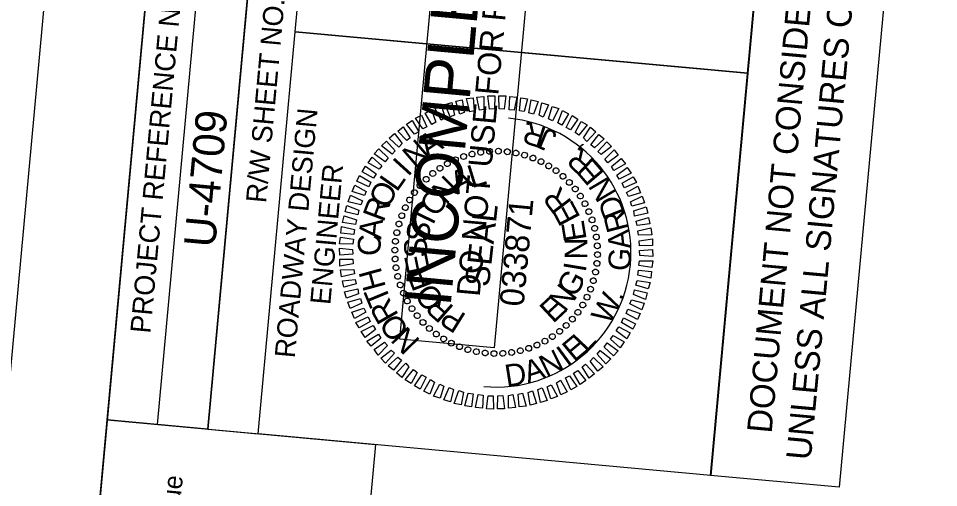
# Model space of a CAD drawing. Extents: x 2011671 to 2012922, y 444832 to 446720.
# Drawn here: x 2011808.5 to 2012036.3, y 446477.1 to 446593.3 of the extents above; entities that cross this region are included whole.
import ezdxf

# ---------------------------------------------------------------- set-up
doc = ezdxf.new("R2010")
doc.units = 0
for name, color, linetype in [('Old_Level_2', 7, 'Continuous'), ('Old_Level_58', 7, 'Continuous'), ('Scratch_Level_0', 7, 'Continuous'), ('Sheet Data Field CELL', 7, 'Continuous'), ('Sheet Plan And Profile CELL', 7, 'Continuous'), ('Sheet Plot Border Outside CELL', 7, 'Continuous'), ('Sheet Professional Seal CELL', 7, 'Continuous'), ('Sheet Profile Grid Minor CELL', 7, 'Continuous'), ('Sheet Sticker Exception Certification CELL', 7, 'Continuous'), ('Sheet Sticker Incomplete CELL', 7, 'Continuous')]:
    doc.layers.add(name, color=color, linetype=linetype)

msp = doc.modelspace()

# ---------------------------------------------------------------- linework, layer by layer
at = {"layer": 'Old_Level_58'}
msp.add_lwpolyline([(2011812.16, 446294.64), (2011830.48, 446493.85), (2011896.89, 446487.74), (2011878.57, 446288.53)], close=True, dxfattribs=at)
at = {"layer": 'Scratch_Level_0'}
msp.add_arc((2011926.78, 446535.36), 33.36, 264.7467, 84.7467, dxfattribs=at)
at = {"layer": 'Sheet Plan And Profile CELL'}
for p, q in [((2011842.98, 446492.7), (2011861.29, 446691.91)), ((2011855.42, 446491.55), (2011873.74, 446690.76)), ((2011877.03, 446590.04), (2011989.01, 446579.74)), ((2011855.42, 446491.55), (2011867.87, 446490.41))]:
    msp.add_line(p, q, dxfattribs=at)
for points in [[(2011848.79, 446693.05), (2011711.46, 445199.36), (2012757.04, 445103.22), (2012894.38, 446596.92)], [(2011830.48, 446493.85), (2011848.79, 446693.05), (2011873.74, 446690.76), (2011855.42, 446491.55)], [(2011877.03, 446590.04), (2011886.19, 446689.62), (2011998.21, 446679.32), (2011989.06, 446579.74)], [(2011867.87, 446490.41), (2011877.03, 446590.04), (2011989.06, 446579.74), (2011979.9, 446480.11)]]:
    msp.add_lwpolyline(points, close=True, dxfattribs=at)
at = {"layer": 'Sheet Plot Border Outside CELL'}
msp.add_lwpolyline([(2012765.92, 444926.66), (2012921.57, 446619.52), (2011826.19, 446720.24), (2011670.54, 445027.38)], close=True, dxfattribs=at)
at = {"layer": 'Sheet Professional Seal CELL'}
for p, q in [((2011920.79, 446559.76), (2011920.79, 446559.76)), ((2011922.94, 446560.17), (2011922.94, 446560.17)), ((2011925.17, 446560.37), (2011925.17, 446560.37)), ((2011927.34, 446560.47), (2011927.34, 446560.47)), ((2011929.53, 446560.32), (2011929.53, 446560.32)), ((2011931.71, 446559.97), (2011931.71, 446559.97)), ((2011916.7, 446558.33), (2011916.7, 446558.33)), ((2011918.73, 446559.15), (2011918.73, 446559.15)), ((2011933.82, 446559.42), (2011933.82, 446559.42)), ((2011935.87, 446558.78), (2011935.87, 446558.78)), ((2011937.89, 446557.89), (2011937.89, 446557.89)), ((2011912.84, 446556.28), (2011912.84, 446556.28)), ((2011914.7, 446557.36), (2011914.7, 446557.36)), ((2011939.8, 446556.81), (2011939.8, 446556.81)), ((2011941.65, 446555.64), (2011941.65, 446555.64)), ((2011909.43, 446553.53), (2011909.43, 446553.53)), ((2011911.06, 446554.93), (2011911.06, 446554.93)), ((2011943.33, 446554.23), (2011943.33, 446554.23)), ((2011907.92, 446551.91), (2011907.92, 446551.91)), ((2011944.95, 446552.72), (2011944.95, 446552.72)), ((2011946.36, 446551.09), (2011946.36, 446551.09)), ((2011905.34, 446548.38), (2011905.34, 446548.38)), ((2011906.51, 446550.23), (2011906.51, 446550.23)), ((2011947.7, 446549.31), (2011947.7, 446549.31)), ((2011904.26, 446546.47), (2011904.26, 446546.47)), ((2011948.78, 446547.45), (2011948.78, 446547.45)), ((2011903.37, 446544.44), (2011903.37, 446544.44)), ((2011949.75, 446545.45), (2011949.75, 446545.45)), ((2011902.73, 446542.39), (2011902.73, 446542.39)), ((2011950.57, 446543.42), (2011950.57, 446543.42)), ((2011902.18, 446540.29), (2011902.18, 446540.29)), ((2011951.19, 446541.35), (2011951.19, 446541.35)), ((2011951.59, 446539.21), (2011951.59, 446539.21)), ((2011901.83, 446538.11), (2011901.83, 446538.11)), ((2011951.79, 446536.98), (2011951.79, 446536.98)), ((2011901.68, 446535.91), (2011901.68, 446535.91)), ((2011926.78, 446535.36), (2011926.78, 446535.36)), ((2011951.89, 446534.81), (2011951.89, 446534.81)), ((2011901.78, 446533.75), (2011901.78, 446533.75)), ((2011951.74, 446532.62), (2011951.74, 446532.62)), ((2011901.98, 446531.52), (2011901.98, 446531.52)), ((2011951.39, 446530.44), (2011951.39, 446530.44)), ((2011902.38, 446529.37), (2011902.38, 446529.37)), ((2011950.84, 446528.33), (2011950.84, 446528.33)), ((2011903, 446527.31), (2011903, 446527.31)), ((2011950.2, 446526.28), (2011950.2, 446526.28)), ((2011903.81, 446525.27), (2011903.81, 446525.27)), ((2011904.79, 446523.28), (2011904.79, 446523.28)), ((2011949.31, 446524.25), (2011949.31, 446524.25)), ((2011905.87, 446521.42), (2011905.87, 446521.42)), ((2011948.23, 446522.34), (2011948.23, 446522.34)), ((2011907.21, 446519.64), (2011907.21, 446519.64)), ((2011945.65, 446518.82), (2011945.65, 446518.82)), ((2011947.06, 446520.49), (2011947.06, 446520.49)), ((2011908.62, 446518), (2011908.62, 446518)), ((2011910.24, 446516.5), (2011910.24, 446516.5)), ((2011944.14, 446517.2), (2011944.14, 446517.2)), ((2011911.92, 446515.09), (2011911.92, 446515.09)), ((2011940.73, 446514.45), (2011940.73, 446514.45)), ((2011942.51, 446515.79), (2011942.51, 446515.79)), ((2011913.77, 446513.91), (2011913.77, 446513.91)), ((2011915.68, 446512.84), (2011915.68, 446512.84)), ((2011917.7, 446511.95), (2011917.7, 446511.95)), ((2011936.87, 446512.39), (2011936.87, 446512.39)), ((2011938.87, 446513.36), (2011938.87, 446513.36)), ((2011919.75, 446511.31), (2011919.75, 446511.31)), ((2011921.86, 446510.76), (2011921.86, 446510.76)), ((2011924.04, 446510.41), (2011924.04, 446510.41)), ((2011926.23, 446510.26), (2011926.23, 446510.26)), ((2011928.4, 446510.36), (2011928.4, 446510.36)), ((2011930.63, 446510.56), (2011930.63, 446510.56)), ((2011932.78, 446510.96), (2011932.78, 446510.96)), ((2011934.84, 446511.58), (2011934.84, 446511.58))]:
    msp.add_line(p, q, dxfattribs=at)
for points in [[(2011920.25, 446570.21), (2011919.4, 446573.5), (2011921.07, 446573.65), (2011921.33, 446570.46)], [(2011922.69, 446570.59), (2011922.03, 446573.81), (2011923.76, 446573.95), (2011923.77, 446570.79)], [(2011925.12, 446570.81), (2011924.72, 446574.11), (2011926.43, 446574.11), (2011926.34, 446570.9)], [(2011927.54, 446570.89), (2011927.44, 446574.17), (2011929.14, 446574.11), (2011928.75, 446570.88)], [(2011930.04, 446570.71), (2011930.18, 446573.96), (2011931.88, 446573.81), (2011931.23, 446570.6)], [(2011932.52, 446570.43), (2011932.92, 446573.66), (2011934.55, 446573.41), (2011933.71, 446570.23)], [(2011913.13, 446568.15), (2011911.64, 446571.1), (2011913.25, 446571.6), (2011914.13, 446568.66)], [(2011915.36, 446568.95), (2011914.14, 446572.02), (2011915.79, 446572.53), (2011916.5, 446569.35)], [(2011917.78, 446569.63), (2011916.77, 446572.79), (2011918.36, 446573.19), (2011918.88, 446570.03)], [(2011934.89, 446569.97), (2011935.48, 446573.13), (2011937.15, 446572.77), (2011936.06, 446569.61)], [(2011937.39, 446569.33), (2011938.07, 446572.38), (2011939.73, 446571.88), (2011938.4, 446568.84)], [(2011939.72, 446568.47), (2011940.65, 446571.49), (2011942.26, 446571), (2011940.73, 446567.97)], [(2011908.66, 446565.95), (2011906.79, 446568.58), (2011908.32, 446569.4), (2011909.66, 446566.46)], [(2011910.82, 446567.06), (2011909.17, 446569.87), (2011910.75, 446570.68), (2011911.88, 446567.66)], [(2011942.04, 446567.5), (2011943.22, 446570.51), (2011944.71, 446569.72), (2011943.04, 446566.86)], [(2011944.14, 446566.3), (2011945.57, 446569.29), (2011947.04, 446568.4), (2011945.19, 446565.7)], [(2011906.58, 446564.64), (2011904.55, 446567.13), (2011905.99, 446568.05), (2011907.64, 446565.24)], [(2011946.34, 446565.1), (2011947.85, 446567.82), (2011949.32, 446566.93), (2011947.23, 446564.41)], [(2011902.72, 446561.43), (2011900.32, 446563.7), (2011901.62, 446564.79), (2011903.55, 446562.3)], [(2011904.63, 446563.06), (2011902.48, 446565.41), (2011903.79, 446566.5), (2011905.49, 446563.73)], [(2011948.37, 446563.71), (2011950.12, 446566.36), (2011951.42, 446565.23), (2011949.19, 446562.83)], [(2011950.22, 446562.03), (2011952.16, 446564.56), (2011953.52, 446563.48), (2011951.11, 446561.29)], [(2011901, 446559.68), (2011898.43, 446561.77), (2011899.65, 446562.96), (2011901.79, 446560.56)], [(2011951.98, 446560.36), (2011954.16, 446562.77), (2011955.35, 446561.56), (2011952.81, 446559.58)], [(2011899.32, 446557.77), (2011896.59, 446559.78), (2011897.76, 446560.98), (2011900.02, 446558.81)], [(2011953.71, 446558.44), (2011955.99, 446560.8), (2011957.02, 446559.45), (2011954.43, 446557.57)], [(2011897.8, 446555.95), (2011895.08, 446557.56), (2011896.07, 446558.97), (2011898.48, 446556.84)], [(2011955.3, 446556.64), (2011957.69, 446558.63), (2011958.78, 446557.33), (2011955.91, 446555.63)], [(2011896.44, 446553.77), (2011893.62, 446555.28), (2011894.46, 446556.76), (2011897.09, 446554.81)], [(2011956.66, 446554.51), (2011959.25, 446556.43), (2011960.17, 446554.99), (2011957.22, 446553.5)], [(2011895.29, 446551.61), (2011892.26, 446553.05), (2011892.98, 446554.39), (2011895.74, 446552.73)], [(2011957.98, 446552.48), (2011960.69, 446554.09), (2011961.52, 446552.71), (2011958.48, 446551.33)], [(2011894.19, 446549.46), (2011891.17, 446550.49), (2011891.81, 446551.98), (2011894.63, 446550.47)], [(2011959.03, 446550.17), (2011961.88, 446551.77), (2011962.54, 446550.15), (2011959.54, 446549.17)], [(2011893.32, 446547.13), (2011890.13, 446547.92), (2011890.68, 446549.58), (2011893.67, 446548.15)], [(2011960.02, 446547.92), (2011962.96, 446549.26), (2011963.51, 446547.65), (2011960.37, 446546.79)], [(2011892.54, 446544.64), (2011889.39, 446545.38), (2011889.79, 446547), (2011892.8, 446545.82)], [(2011960.87, 446545.63), (2011963.88, 446546.66), (2011964.34, 446545.12), (2011961.05, 446544.36)], [(2011891.92, 446542.28), (2011888.7, 446542.78), (2011889.15, 446544.4), (2011892.23, 446543.46)], [(2011961.44, 446543.12), (2011964.53, 446543.99), (2011964.84, 446542.41), (2011961.69, 446542.04)], [(2011891.54, 446539.81), (2011888.31, 446540.11), (2011888.51, 446541.74), (2011891.7, 446541)], [(2011961.87, 446540.67), (2011965.1, 446541.43), (2011965.29, 446539.7), (2011962.02, 446539.6)], [(2011891.27, 446537.42), (2011888.01, 446537.47), (2011888.22, 446539.11), (2011891.43, 446538.61)], [(2011962.2, 446538.23), (2011965.46, 446538.74), (2011965.45, 446537.08), (2011962.24, 446537.02)], [(2011891.29, 446534.91), (2011888.06, 446534.66), (2011888.01, 446536.37), (2011891.25, 446536.12)], [(2011962.28, 446535.81), (2011965.51, 446536.07), (2011965.56, 446534.36), (2011962.31, 446534.61)], [(2011891.37, 446532.49), (2011888.11, 446531.99), (2011888.12, 446533.65), (2011891.33, 446533.7)], [(2011962.3, 446533.3), (2011965.55, 446533.25), (2011965.35, 446531.62), (2011962.14, 446532.11)], [(2011891.7, 446530.05), (2011888.47, 446529.3), (2011888.28, 446531.02), (2011891.55, 446531.12)], [(2011962.03, 446530.92), (2011965.26, 446530.62), (2011965.06, 446528.98), (2011961.87, 446529.73)], [(2011892.13, 446527.6), (2011889.04, 446526.73), (2011888.73, 446528.32), (2011891.88, 446528.68)], [(2011961.65, 446528.44), (2011964.87, 446527.94), (2011964.42, 446526.33), (2011961.34, 446527.26)], [(2011892.7, 446525.09), (2011889.69, 446524.06), (2011889.23, 446525.61), (2011892.52, 446526.36)], [(2011961.03, 446526.09), (2011964.17, 446525.35), (2011963.77, 446523.73), (2011960.77, 446524.91)], [(2011893.55, 446522.8), (2011890.61, 446521.47), (2011890.06, 446523.07), (2011893.2, 446523.94)], [(2011960.25, 446523.6), (2011963.44, 446522.8), (2011962.88, 446521.15), (2011959.9, 446522.58)], [(2011894.54, 446520.55), (2011891.69, 446518.96), (2011891.03, 446520.57), (2011894.03, 446521.55)], [(2011959.38, 446521.27), (2011962.4, 446520.24), (2011961.76, 446518.74), (2011958.94, 446520.26)], [(2011895.59, 446518.25), (2011892.88, 446516.64), (2011892.05, 446518.02), (2011895.09, 446519.4)], [(2011958.28, 446519.11), (2011961.31, 446517.68), (2011960.58, 446516.34), (2011957.83, 446518)], [(2011896.91, 446516.22), (2011894.32, 446514.3), (2011893.4, 446515.74), (2011896.35, 446517.22)], [(2011957.13, 446516.96), (2011959.95, 446515.44), (2011959.11, 446513.96), (2011956.48, 446515.91)], [(2011898.27, 446514.08), (2011895.87, 446512.09), (2011894.79, 446513.4), (2011897.66, 446515.09)], [(2011955.77, 446514.77), (2011958.49, 446513.17), (2011957.5, 446511.75), (2011955.09, 446513.88)], [(2011899.86, 446512.28), (2011897.58, 446509.93), (2011896.55, 446511.28), (2011899.13, 446513.15)], [(2011954.25, 446512.95), (2011956.98, 446510.95), (2011955.81, 446509.75), (2011953.55, 446511.91)], [(2011901.59, 446510.36), (2011899.41, 446507.95), (2011898.22, 446509.17), (2011900.76, 446511.14)], [(2011952.57, 446511.05), (2011955.14, 446508.96), (2011953.92, 446507.76), (2011951.78, 446510.17)], [(2011903.34, 446508.7), (2011901.4, 446506.16), (2011900.05, 446507.24), (2011902.46, 446509.43)], [(2011905.2, 446507.02), (2011903.45, 446504.37), (2011902.15, 446505.49), (2011904.38, 446507.9)], [(2011948.94, 446507.67), (2011951.09, 446505.31), (2011949.78, 446504.23), (2011948.08, 446506.99)], [(2011950.85, 446509.3), (2011953.25, 446507.02), (2011951.95, 446505.94), (2011950.02, 446508.42)], [(2011907.23, 446505.63), (2011905.72, 446502.9), (2011904.25, 446503.79), (2011906.34, 446506.31)], [(2011946.99, 446506.09), (2011949.02, 446503.59), (2011947.58, 446502.67), (2011945.93, 446505.48)], [(2011909.43, 446504.42), (2011908, 446501.44), (2011906.53, 446502.33), (2011908.38, 446505.02)], [(2011911.53, 446503.22), (2011910.35, 446500.22), (2011908.86, 446501.01), (2011910.53, 446503.87)], [(2011913.85, 446502.26), (2011912.92, 446499.23), (2011911.31, 446499.73), (2011912.84, 446502.75)], [(2011942.75, 446503.67), (2011944.4, 446500.85), (2011942.82, 446500.05), (2011941.69, 446503.06)], [(2011944.91, 446504.77), (2011946.78, 446502.14), (2011945.25, 446501.33), (2011943.91, 446504.26)], [(2011916.18, 446501.39), (2011915.5, 446498.34), (2011913.84, 446498.84), (2011915.17, 446501.89)], [(2011918.68, 446500.76), (2011918.09, 446497.6), (2011916.42, 446497.95), (2011917.51, 446501.12)], [(2011921.05, 446500.29), (2011920.65, 446497.06), (2011919.02, 446497.31), (2011919.86, 446500.5)], [(2011933.32, 446500.52), (2011934.17, 446497.23), (2011932.5, 446497.08), (2011932.24, 446500.27)], [(2011935.78, 446501.09), (2011936.8, 446497.94), (2011935.21, 446497.53), (2011934.69, 446500.69)], [(2011938.21, 446501.78), (2011939.43, 446498.7), (2011937.78, 446498.2), (2011937.07, 446501.38)], [(2011940.44, 446502.57), (2011941.93, 446499.63), (2011940.32, 446499.12), (2011939.44, 446502.06)], [(2011923.53, 446500.01), (2011923.39, 446496.76), (2011921.69, 446496.92), (2011922.34, 446500.12)], [(2011926.03, 446499.83), (2011926.13, 446496.56), (2011924.43, 446496.62), (2011924.82, 446499.84)], [(2011928.45, 446499.91), (2011928.85, 446496.61), (2011927.14, 446496.62), (2011927.23, 446499.82)], [(2011930.88, 446500.14), (2011931.53, 446496.92), (2011929.81, 446496.77), (2011929.8, 446499.94)]]:
    msp.add_lwpolyline(points, close=True, dxfattribs=at)
for centre, major_axis in [((2011918.72, 446559.11), (-0.231, 0.682)), ((2011920.82, 446559.72), (-0.171, 0.699)), ((2011922.97, 446560.15), (-0.109, 0.712)), ((2011925.15, 446560.39), (-0.047, 0.718)), ((2011927.33, 446560.44), (0.016, 0.72)), ((2011929.52, 446560.29), (0.078, 0.716)), ((2011931.68, 446559.96), (0.141, 0.706)), ((2011933.8, 446559.44), (0.202, 0.691)), ((2011914.72, 446557.35), (-0.346, 0.631)), ((2011916.69, 446558.32), (-0.29, 0.659)), ((2011935.88, 446558.74), (0.261, 0.671)), ((2011937.88, 446557.86), (0.318, 0.646)), ((2011939.8, 446556.8), (0.374, 0.616)), ((2011911.09, 446554.92), (-0.451, 0.562)), ((2011912.85, 446556.22), (-0.4, 0.599)), ((2011941.62, 446555.59), (0.426, 0.581)), ((2011909.44, 446553.48), (-0.498, 0.52)), ((2011943.32, 446554.22), (0.475, 0.541)), ((2011944.9, 446552.7), (0.52, 0.498)), ((2011906.56, 446550.19), (-0.581, 0.426)), ((2011907.93, 446551.9), (-0.541, 0.475)), ((2011946.35, 446551.06), (0.562, 0.451)), ((2011905.34, 446548.37), (-0.616, 0.374)), ((2011947.64, 446549.3), (0.599, 0.4)), ((2011904.29, 446546.46), (-0.646, 0.318)), ((2011948.77, 446547.42), (0.631, 0.346)), ((2011949.74, 446545.46), (0.659, 0.29)), ((2011903.41, 446544.45), (-0.671, 0.261)), ((2011950.53, 446543.42), (0.682, 0.231)), ((2011902.71, 446542.38), (-0.691, 0.202)), ((2011951.15, 446541.32), (0.699, 0.171)), ((2011902.19, 446540.26), (-0.706, 0.141)), ((2011951.57, 446539.18), (0.712, 0.109)), ((2011901.85, 446538.09), (-0.716, 0.078)), ((2011951.81, 446537), (0.718, 0.047)), ((2011901.71, 446535.91), (-0.72, 0.016)), ((2011951.86, 446534.81), (0.72, -0.016)), ((2011901.76, 446533.72), (-0.718, -0.047)), ((2011951.72, 446532.63), (0.716, -0.078)), ((2011902, 446531.55), (-0.712, -0.109)), ((2011902.42, 446529.4), (-0.699, -0.171)), ((2011951.38, 446530.47), (0.706, -0.141)), ((2011903.04, 446527.3), (-0.682, -0.231)), ((2011950.86, 446528.34), (0.691, -0.202)), ((2011903.83, 446525.26), (-0.659, -0.29)), ((2011950.16, 446526.27), (0.671, -0.261)), ((2011904.8, 446523.3), (-0.631, -0.346)), ((2011949.28, 446524.27), (0.646, -0.318)), ((2011905.93, 446521.43), (-0.599, -0.4)), ((2011947.01, 446520.53), (0.581, -0.426)), ((2011948.23, 446522.35), (0.616, -0.374)), ((2011907.22, 446519.67), (-0.562, -0.451)), ((2011908.67, 446518.02), (-0.52, -0.498)), ((2011945.64, 446518.83), (0.541, -0.475)), ((2011910.25, 446516.51), (-0.475, -0.541)), ((2011942.48, 446515.8), (0.451, -0.562)), ((2011944.13, 446517.24), (0.498, -0.52)), ((2011911.95, 446515.14), (-0.426, -0.581)), ((2011913.77, 446513.92), (-0.374, -0.616)), ((2011938.85, 446513.37), (0.346, -0.631)), ((2011940.72, 446514.51), (0.4, -0.599)), ((2011915.69, 446512.87), (-0.318, -0.646)), ((2011917.69, 446511.99), (-0.261, -0.671)), ((2011919.77, 446511.28), (-0.202, -0.691)), ((2011934.85, 446511.61), (0.231, -0.682)), ((2011936.88, 446512.41), (0.29, -0.659)), ((2011921.89, 446510.76), (-0.141, -0.706)), ((2011924.05, 446510.43), (-0.078, -0.716)), ((2011926.24, 446510.29), (-0.016, -0.72)), ((2011928.42, 446510.34), (0.047, -0.718)), ((2011930.6, 446510.57), (0.109, -0.712)), ((2011932.74, 446511), (0.171, -0.699))]:
    msp.add_ellipse(centre, major_axis=major_axis, ratio=0.999708, dxfattribs=at)
at = {"layer": 'Sheet Sticker Exception Certification CELL'}
for p, q in [((2011979.88, 446480.11), (2011998.2, 446679.32)), ((2012030.04, 446676.39), (2012011.73, 446477.18)), ((2012011.73, 446477.18), (2011979.88, 446480.11))]:
    msp.add_line(p, q, dxfattribs=at)
at = {"layer": 'Sheet Sticker Incomplete CELL'}
msp.add_lwpolyline([(2011926.32, 446511.7), (2011902.91, 446513.85), (2011916.37, 446660.23), (2011939.77, 446658.08)], close=True, dxfattribs=at)

# ---------------------------------------------------------------- texts
at = {"layer": 'Old_Level_2'}
msp.add_text('1 Glenwood Avenue', height=4.6576, rotation=84.7467, dxfattribs=at).set_placement((2011844.11, 446424.1))
at = {"layer": 'Sheet Data Field CELL'}
msp.add_text('U-4709', height=7.75, rotation=84.7467, dxfattribs=at).set_placement((2011857.18, 446536.38))
at = {"layer": 'Sheet Plan And Profile CELL'}
for s, height, p in [('PROJECT REFERENCE NO.', 5.0001, (2011841.17, 446515.16)), ('R/W SHEET NO.', 5.0001, (2011869.8, 446547.47)), ('ROADWAY DESIGN', 5.0001, (2011876.92, 446509.06)), ('ENGINEER', 5, (2011885.71, 446522.26))]:
    msp.add_text(s, height=height, rotation=84.7467, dxfattribs=at).set_placement(p)
at = {"layer": 'Sheet Professional Seal CELL'}
for s, height, rotation, p in [('A', 5.64, 33.3638, (2011909.89, 446558.61)), ('N', 5.64, 40.5656, (2011906.68, 446555.94)), ('I', 5.64, 47.7668, (2011904.94, 446553.94)), ('A', 5.64, 26.5069, (2011917.15, 446549.6)), ('L', 5.64, 17.1475, (2011920.76, 446551.23)), ('L', 5.64, 54.9675, (2011902.18, 446550.13)), ('N', 5.64, 45.2233, (2011914.3, 446547)), ('O', 5.64, 62.1678, (2011899.94, 446545.91)), ('O', 5.64, 54.5801, (2011912, 446543.85)), ('R', 5.64, 127.2281, (2011945.75, 446547.78)), ('R', 5.64, 69.3678, (2011898.88, 446542.65)), ('SEAL', 5.998, 83.7467, (2011924.98, 446526.64)), ('E', 5.64, 117.8707, (2011947.77, 446544.03)), ('I', 5.64, 63.9363, (2011911.12, 446541.92)), ('A', 5.64, 83.767, (2011898.3, 446538.48)), ('S', 5.64, 82.6471, (2011910.03, 446537.71)), ('E', 5.64, 99.1584, (2011949.22, 446538.57)), ('C', 5.64, 90.9665, (2011898.24, 446534.52)), ('S', 5.64, 92.0023, (2011909.75, 446534.12)), ('N', 5.64, 89.803, (2011949.37, 446533.59)), ('E', 5.64, 101.3577, (2011910.48, 446530.59)), ('I', 5.64, 80.4479, (2011948.91, 446530.27)), ('H', 5.64, 105.3661, (2011899.53, 446526.77)), ('F', 5.64, 110.7137, (2011911.68, 446527.26)), ('G', 5.64, 61.7369, (2011946.42, 446523.92)), ('T', 5.64, 112.5664, (2011900.88, 446523.38)), ('O', 5.64, 129.4279, (2011914.32, 446523.71)), ('N', 5.64, 52.3806, (2011943.83, 446520.34)), ('R', 5.64, 119.7672, (2011902.76, 446519.8)), ('R', 5.64, 138.7863, (2011916.59, 446521.74)), ('E', 5.64, 43.0235, (2011940.87, 446517.6)), ('O', 5.64, 126.9684, (2011905.53, 446516.08)), ('P', 5.64, 148.1455, (2011919.63, 446519.85)), ('N', 5.64, 134.1702, (2011908.21, 446513.52))]:
    msp.add_text(s, height=height, rotation=rotation, dxfattribs=at).set_placement(p)
at = {"layer": 'Sheet Profile Grid Minor CELL'}
for s, height, rotation, p in [('R', 5.5, 162.1007, (2011939.57, 446566.29)), ('.', 5.5, 169.0272, (2011935.75, 446567.61)), ('J', 5.5, 157.2322, (2011942.15, 446565.1)), (',', 5.5, 144.0519, (2011948.53, 446560.81)), ('R', 5.5, 137.1254, (2011951.44, 446558)), ('E', 5.5, 130.5425, (2011953.87, 446555.03)), ('N', 5.5, 120.6107, (2011956.85, 446550.06)), ('D', 5.5, 111.4661, (2011958.81, 446545.09)), ('033871', 5.998, 84.7467, (2011933.58, 446521.79)), ('R', 5.5, 104.5397, (2011959.75, 446541.16)), ('A', 5.5, 96.3539, (2011960.24, 446536.41)), ('G', 5.5, 86.4222, (2011959.92, 446530.62)), ('W', 5.5, 61.6358, (2011954.88, 446517.17)), ('.', 5.5, 73.2419, (2011957.96, 446523.19)), ('E', 5.5, 39.7975, (2011946.09, 446508.02)), ('L', 5.5, 46.3805, (2011949.1, 446510.42)), ('I', 5.5, 36.277, (2011944.38, 446506.89)), ('N', 5.5, 26.3453, (2011939.2, 446504.28)), ('D', 5.5, 9.0149, (2011929.38, 446501.99)), ('A', 5.5, 18.1595, (2011934.65, 446502.83))]:
    msp.add_text(s, height=height, rotation=rotation, dxfattribs=at).set_placement(p)
at = {"layer": 'Sheet Sticker Exception Certification CELL'}
for s, p in [('UNLESS ALL SIGNATURES COMPLETED', (2012004.66, 446483.75)), ('DOCUMENT NOT CONSIDERED FINAL', (2011994.97, 446490.4))]:
    msp.add_text(s, height=6.124, rotation=84.7467, dxfattribs=at).set_placement(p)
at = {"layer": 'Sheet Sticker Incomplete CELL'}
for s, height, p in [('INCOMPLETE PLANS', 11.52, (2011915.48, 446521.68)), ('DO NOT USE FOR R/W ACQUISITION', 5.76, (2011922.7, 446524.28))]:
    msp.add_text(s, height=height, rotation=84.7467, dxfattribs=at).set_placement(p)

doc.saveas('drawing.dxf')
